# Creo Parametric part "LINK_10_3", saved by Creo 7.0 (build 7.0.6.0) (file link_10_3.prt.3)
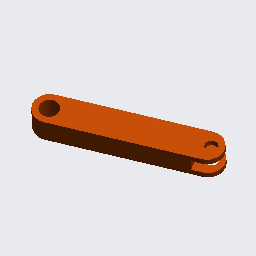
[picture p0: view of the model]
Units: millimeter Newton Second (mmNs); MM, TONNE, SECS

Created from: XX_MMNS_PART_SOLID_ABS.PRT

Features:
  1. datum plane "RIGHT"
  2. datum plane "TOP"
  3. datum plane "FRONT"
  4. coordinate system
  5. extrusion "Extrude 1"
  6. extruded cut "Extrude 2"
  7. extruded cut "Extrude 3"
  8. extruded cut "Extrude 4"

Surfaces: 7 plane, 4 cylinder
